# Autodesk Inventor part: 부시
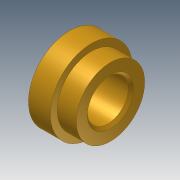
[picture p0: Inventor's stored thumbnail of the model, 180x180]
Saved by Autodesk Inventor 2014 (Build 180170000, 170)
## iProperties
Created: 2011-04
Part Number: 부시
Document SubType Name: Modeling
Density: 1 g/cm^3
Material: 일반
Appearance: 황동 - 새틴
Author: pww
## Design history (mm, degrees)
sketch "스케치1"
  geometry: L1 (0, 0)-(15, 0); L2 (0, 7.5)-(15, 7.5); L3 (15, 7.5)-(15, 12.5); L4 (15, 12.5)-(8, 12.5); L5 (8, 12.5)-(8, 15); L6 (8, 15)-(0, 15); L7 (0, 15)-(0, 7.5)
  constraints: 14 end point, 4 parallel, 2 vertical alignment, 1 horizontal, 1 perpendicular, 1 vertical
  dimensions: "d0" = 15 distance of L1.start L1.end; "d1" = 15 diameter of L2 L1; "d2" = 25 diameter of L4 L1; "d3" = 8 distance of L5.end L6.end; "d4" = 30 diameter of L6 L1
revolve "회전1" sketch "스케치1" stored, may be unused: angle "d5" = 90 deg
chamfer "모따기1" distance "d6" = 1; stored, may be unused: second distance "d7" = 2, angle "d8" = 45 deg
node "솔리드1"
